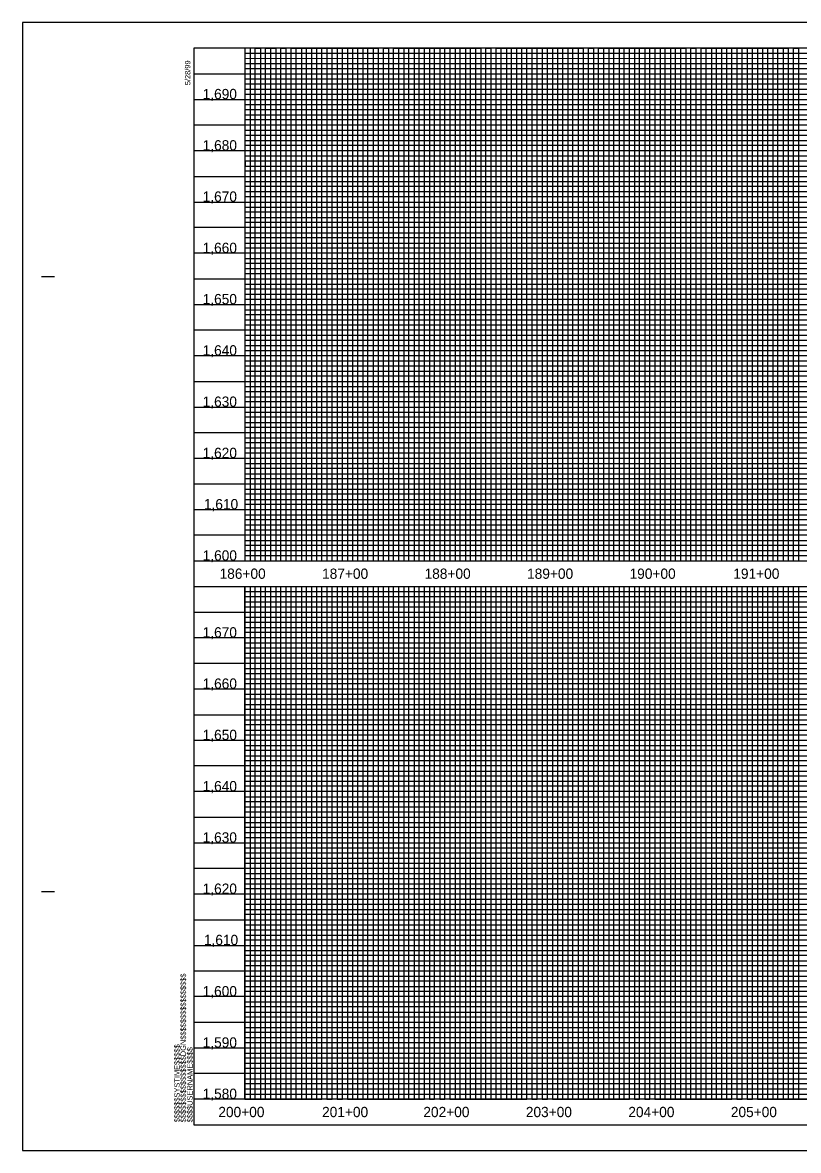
# Model space of a CAD drawing. Extents: x 505602 to 507286, y 483109 to 484209.
# Drawn here: x 505602 to 506359, y 483109 to 484209 of the extents above; entities that cross this region are included whole.
import ezdxf

# ---------------------------------------------------------------- set-up
doc = ezdxf.new("R2010")
doc.units = 0
for name, color, linetype in [('Exist Vertical Profile Vertical Axis Label', 7, 'Continuous'), ('Sheet Layout Profile Border Port 1', 7, 'Continuous'), ('Sheet Layout Profile Border Port 2', 7, 'Continuous'), ('Sheet Plot Border Outside CELL', 7, 'Continuous'), ('Sheet Profile CELL', 7, 'Continuous'), ('Sheet Profile Grid Major CELL', 7, 'Continuous'), ('Sheet Profile Grid Middle CELL', 7, 'Continuous'), ('Sheet Profile Grid Minor CELL', 7, 'Continuous')]:
    doc.layers.add(name, color=color, linetype=linetype)

msp = doc.modelspace()

# ---------------------------------------------------------------- linework, layer by layer
at = {"layer": 'Sheet Layout Profile Border Port 1'}
msp.add_lwpolyline([(505819.1, 484183.7), (505819.1, 483683.7), (507219.1, 483683.7), (507219.1, 484022.7), (507069, 484022.7), (507069, 484183.7)], close=True, dxfattribs=at)
at = {"layer": 'Sheet Layout Profile Border Port 2'}
msp.add_lwpolyline([(505819.1, 483658.7), (507219.1, 483658.7), (507219.1, 483158.7), (505819.1, 483158.7)], close=True, dxfattribs=at)
at = {"layer": 'Sheet Plot Border Outside CELL'}
msp.add_lwpolyline([(505602.1, 483108.7), (507286.1, 483108.7), (507286.1, 484208.7), (505602.1, 484208.7)], close=True, dxfattribs=at)
at = {"layer": 'Sheet Profile CELL'}
for p, q in [((505620.6, 483961.2), (505633.1, 483961.2)), ((505769.1, 483683.7), (507269.1, 483683.7)), ((505769.1, 483658.7), (507269.1, 483658.7)), ((505620.6, 483361.2), (505633.1, 483361.2)), ((507269.1, 483158.7), (505769.1, 483158.7)), ((505769.1, 483133.7), (507269.1, 483133.7)), ((505769.1, 483133.7), (505769.1, 483133.7)), ((505769.1, 483133.7), (505769.1, 483133.7)), ((505769.1, 483133.7), (505769.1, 483133.7)), ((505769.1, 483133.7), (505769.1, 483133.7)), ((505769.1, 483133.7), (505769.1, 483133.7)), ((505769.1, 483133.7), (505769.1, 483133.7)), ((505769.1, 483133.7), (505769.1, 483133.7))]:
    msp.add_line(p, q, dxfattribs=at)
msp.add_lwpolyline([(507269.1, 484183.7), (505769.1, 484183.7), (505769.1, 483133.7), (507269.1, 483133.7)], close=True, dxfattribs=at)
msp.add_lwpolyline([(505806.6, 483133.7), (505806.6, 483133.7)], dxfattribs=at)
at = {"layer": 'Sheet Profile Grid Major CELL'}
msp.add_line((506269.1, 483658.7), (506319.1, 483658.7), dxfattribs=at)
for points in [[(505819.1, 484183.7), (505819.1, 483683.7), (505869.1, 483683.7), (505869.1, 484183.7), (505919.1, 484183.7), (505919.1, 483683.7), (505969.1, 483683.7), (505969.1, 484183.7), (506019.1, 484183.7), (506019.1, 483683.7), (506069.1, 483683.7), (506069.1, 484183.7), (506119.1, 484183.7), (506119.1, 483683.7), (506169.1, 483683.7), (506169.1, 484183.7), (506219.1, 484183.7), (506219.1, 483683.7), (506269.1, 483683.7), (506269.1, 484183.7), (506319.1, 484183.7), (506319.1, 483683.7), (506369.1, 483683.7)], [(505769.1, 484133.7), (507069.1, 484133.7)], [(507069.1, 484083.7), (505769.1, 484083.7), (505769.1, 484033.7), (507069.1, 484033.7)], [(507269.1, 483983.7), (505769.1, 483983.7), (505769.1, 483933.7), (507269.1, 483933.7)], [(507269.1, 483883.7), (505769.1, 483883.7), (505769.1, 483833.7), (507269.1, 483833.7)], [(507269.1, 483783.7), (505769.1, 483783.7), (505769.1, 483783.7), (505769.1, 483733.7), (507269.1, 483733.7)], [(505819.1, 483658.7), (505819.1, 483158.7), (505869.1, 483158.7), (505869.1, 483658.7), (505919.1, 483658.7), (505919.1, 483158.7), (505969.1, 483158.7), (505969.1, 483658.7), (506019.1, 483658.7), (506019.1, 483158.7), (506069.1, 483158.7), (506069.1, 483658.7), (506119.1, 483658.7), (506119.1, 483158.7), (506169.1, 483158.7), (506169.1, 483658.7), (506219.1, 483658.7), (506219.1, 483158.7), (506269.1, 483158.7), (506269.1, 483658.7), (506319.1, 483658.7), (506319.1, 483158.7), (506369.1, 483158.7)], [(507269.1, 483608.7), (505769.1, 483608.7)], [(507269.1, 483558.7), (505769.1, 483558.7), (505769.1, 483508.7), (507269.1, 483508.7)], [(507269.1, 483458.7), (505769.1, 483458.7), (505769.1, 483408.7), (507269.1, 483408.7)], [(507269.1, 483358.7), (505769.1, 483358.7), (505769.1, 483308.7), (507269.1, 483308.7)], [(507269.1, 483258.7), (505769.1, 483258.7), (505769.1, 483258.7), (505769.1, 483208.7), (507269.1, 483208.7)], [(507269.1, 483158.7), (505769.1, 483158.7)]]:
    msp.add_lwpolyline(points, dxfattribs=at)
at = {"layer": 'Sheet Profile Grid Middle CELL'}
msp.add_line((505769.1, 484158.7), (507069, 484158.7), dxfattribs=at)
for points in [[(505844.1, 484183.7), (505844.1, 483683.7), (505894.1, 483683.7), (505894.1, 484183.7), (505944.1, 484183.7), (505944.1, 483683.7), (505994.1, 483683.7), (505994.1, 484183.7), (506044.1, 484183.7), (506044.1, 483683.7), (506094.1, 483683.7), (506094.1, 484183.7), (506144.1, 484183.7), (506144.1, 483683.7), (506194.1, 483683.7), (506194.1, 484183.7), (506244.1, 484183.7), (506244.1, 483683.7), (506294.1, 483683.7), (506294.1, 484183.7), (506344.1, 484183.7), (506344.1, 483683.7), (506394.1, 483683.7)], [(507069.1, 484108.7), (505769.1, 484108.7), (505769.1, 484058.7), (507069.1, 484058.7)], [(507269.1, 484008.7), (505769.1, 484008.7), (505769.1, 483958.7), (507094.1, 483958.7)], [(507269.1, 483908.7), (505769.1, 483908.7), (505769.1, 483858.7), (507269.1, 483858.7)], [(507269.1, 483808.7), (505769.1, 483808.7), (505769.1, 483758.7), (507269.1, 483758.7)], [(507269.1, 483708.7), (505769.1, 483708.7)], [(505794.1, 483658.7), (505844.1, 483658.7), (505844.1, 483158.7), (505894.1, 483158.7), (505894.1, 483658.7), (505944.1, 483658.7), (505944.1, 483158.7), (505994.1, 483158.7), (505994.1, 483658.7), (506044.1, 483658.7), (506044.1, 483158.7), (506094.1, 483158.7), (506094.1, 483658.7), (506144.1, 483658.7), (506144.1, 483158.7), (506194.1, 483158.7), (506194.1, 483658.7), (506244.1, 483658.7), (506244.1, 483158.7), (506294.1, 483158.7), (506294.1, 483658.7), (506344.1, 483658.7), (506344.1, 483158.7), (506394.1, 483158.7)], [(505769.1, 483633.7), (507269.1, 483633.7)], [(507269.1, 483583.7), (505769.1, 483583.7), (505769.1, 483533.7), (507269.1, 483533.7)], [(507269.1, 483483.7), (505769.1, 483483.7), (505769.1, 483433.7), (507269.1, 483433.7)], [(507269.1, 483383.7), (505769.1, 483383.7), (505769.1, 483333.7), (507269.1, 483333.7)], [(507269.1, 483283.7), (505769.1, 483283.7), (505769.1, 483233.7), (507269.1, 483233.7)], [(507269.1, 483183.7), (505769.1, 483183.7)]]:
    msp.add_lwpolyline(points, dxfattribs=at)
at = {"layer": 'Sheet Profile Grid Minor CELL'}
for p, q in [((505819.1, 484178.7), (507069.1, 484178.7)), ((505819.1, 484173.7), (505819.1, 484173.7)), ((507069.1, 484173.7), (505819.1, 484173.4)), ((505819.1, 484168.7), (507069.1, 484168.7)), ((507069, 484048.7), (505819.1, 484048.7)), ((507069.1, 484043.7), (505819.1, 484043.7)), ((507069.1, 484038.7), (505819.1, 484038.7)), ((505819.1, 484028.7), (507069.1, 484028.7)), ((507069.1, 484023.7), (505819.1, 484023.7)), ((505819.1, 484018.7), (507219.1, 484018.7)), ((507219.1, 483998.7), (505819.1, 483998.7)), ((505819.1, 483993.7), (507219.1, 483993.7)), ((507219.1, 483973.7), (505819.1, 483973.7)), ((505819.1, 483968.7), (507219.1, 483968.7)), ((507219.1, 483948.7), (505819.1, 483948.7)), ((505819.1, 483943.7), (507219.1, 483943.7)), ((507219.1, 483938.7), (505819.1, 483938.7)), ((505819.1, 483928.7), (507219.1, 483928.7)), ((507219.1, 483923.7), (505819.1, 483923.7)), ((505819.1, 483918.7), (507219.1, 483918.7)), ((507219.1, 483913.7), (505819.1, 483913.7)), ((505819.1, 483903.7), (507219.1, 483903.7)), ((507219.1, 483898.7), (505819.1, 483898.7)), ((505819.1, 483893.7), (507219.1, 483893.7)), ((507219.1, 483888.7), (505819.1, 483888.7)), ((505819.1, 483878.7), (507219.1, 483878.7)), ((507219.1, 483873.7), (505819.1, 483873.7)), ((505819.1, 483868.7), (507219.1, 483868.7)), ((507219.1, 483863.7), (505819.1, 483863.7)), ((505819.1, 483853.7), (507219.1, 483853.7)), ((507219.1, 483848.7), (505819.1, 483848.7)), ((505819.1, 483843.7), (507219.1, 483843.7)), ((507219.1, 483838.7), (505819.1, 483838.7)), ((505819.1, 483828.7), (507219.1, 483828.7)), ((507219.1, 483823.7), (505819.1, 483823.7)), ((505819.1, 483818.7), (507219.1, 483818.7)), ((507219.1, 483813.7), (505819.1, 483813.7)), ((505819.1, 483803.7), (507219.1, 483803.7)), ((507219.1, 483798.7), (505819.1, 483798.7)), ((507219.1, 483793.7), (505819.1, 483793.7)), ((507219.1, 483788.7), (505819.1, 483788.7)), ((505819.1, 483778.7), (507219.1, 483778.7)), ((507219.1, 483773.7), (505819.1, 483773.7)), ((505819.1, 483768.7), (507219.1, 483768.7)), ((507219.1, 483763.7), (505819.1, 483763.7)), ((505819.1, 483753.7), (507219.1, 483753.7)), ((507219.1, 483748.7), (505819.1, 483748.7)), ((505819.1, 483743.7), (507219.1, 483743.7)), ((507219.1, 483738.7), (505819.1, 483738.7)), ((505819.1, 483728.7), (507219.1, 483728.7)), ((507219.1, 483723.7), (505819.1, 483723.7)), ((505819.1, 483718.7), (507219.1, 483718.7)), ((507219.1, 483713.7), (505819.1, 483713.7)), ((505819.1, 483703.7), (507219.1, 483703.7)), ((507219.1, 483698.7), (505819.1, 483698.7)), ((505819.1, 483693.7), (507219.1, 483693.7)), ((505819.1, 483653.7), (507219.1, 483653.7)), ((507219.1, 483648.7), (505819.1, 483648.7)), ((505819.1, 483643.7), (507219.1, 483643.7)), ((507219.1, 483638.7), (505819.1, 483638.7)), ((505819.1, 483628.7), (507219.1, 483628.7)), ((507219.1, 483623.7), (505819.1, 483623.7)), ((505819.1, 483618.7), (507219.1, 483618.7)), ((507219.1, 483613.7), (505819.1, 483613.7)), ((505819.1, 483603.7), (507219.1, 483603.7)), ((507219.1, 483598.7), (505819.1, 483598.7)), ((505819.1, 483593.7), (507219.1, 483593.7)), ((507219.1, 483588.7), (505819.1, 483588.7)), ((505819.1, 483578.7), (507219.1, 483578.7)), ((507219.1, 483573.7), (505819.1, 483573.7)), ((505819.1, 483568.7), (507219.1, 483568.7)), ((507219.1, 483563.7), (505819.1, 483563.7)), ((505819.1, 483553.7), (507219.1, 483553.7)), ((507219.1, 483548.7), (505819.1, 483548.7)), ((505819.1, 483543.7), (507219.1, 483543.7)), ((507219.1, 483538.7), (505819.1, 483538.7)), ((505819.1, 483528.7), (507219.1, 483528.7)), ((507219.1, 483523.7), (505819.1, 483523.7)), ((505819.1, 483518.7), (507219.1, 483518.7)), ((507219.1, 483513.7), (505819.1, 483513.7)), ((505819.1, 483503.7), (507219.1, 483503.7)), ((507219.1, 483498.7), (505819.1, 483498.7)), ((505819.1, 483493.7), (507219.1, 483493.7)), ((507219.1, 483488.7), (505819.1, 483488.7)), ((505819.1, 483478.7), (507219.1, 483478.7)), ((507219.1, 483473.7), (505819.1, 483473.7)), ((505819.1, 483468.7), (507219.1, 483468.7)), ((507219.1, 483463.7), (505819.1, 483463.9)), ((505819.1, 483453.7), (507219.1, 483453.7)), ((507219.1, 483448.7), (505819.1, 483448.7)), ((505819.1, 483443.7), (507219.1, 483443.7)), ((507219.1, 483438.7), (505819.1, 483438.7)), ((505819.1, 483428.7), (507219.1, 483428.7)), ((507219.1, 483423.7), (505819.1, 483423.7)), ((505819.1, 483418.7), (507219.1, 483418.7)), ((507219.1, 483413.7), (505819.1, 483413.7)), ((505819.1, 483403.7), (507219.1, 483403.7)), ((507219.1, 483398.7), (505819.1, 483398.7)), ((505819.1, 483393.7), (507219.1, 483393.7)), ((507219.1, 483388.7), (505819.1, 483388.7)), ((505819.1, 483378.7), (507219.1, 483378.7)), ((507219.1, 483373.7), (505819.1, 483373.7)), ((505819.1, 483368.7), (507219.1, 483368.7)), ((507219.1, 483363.7), (505819.1, 483363.7)), ((505819.1, 483353.7), (507219.1, 483353.7)), ((507219.1, 483348.7), (505819.1, 483348.7)), ((505819.1, 483343.7), (507219.1, 483343.7)), ((507219.1, 483338.7), (505819.1, 483338.7)), ((505819.1, 483328.7), (507219.1, 483328.7)), ((507219.1, 483323.7), (505819.1, 483323.7)), ((505819.1, 483318.7), (507219.1, 483318.7)), ((507219.1, 483313.7), (505819.1, 483313.7)), ((505819.1, 483303.7), (507219.1, 483303.7)), ((507219.1, 483298.7), (505819.1, 483298.7)), ((505819.1, 483293.7), (507219.1, 483293.7)), ((507219.1, 483288.7), (505819.1, 483288.7)), ((505819.1, 483278.7), (507219.1, 483278.7)), ((507219.1, 483273.7), (505819.1, 483273.7)), ((505819.1, 483268.7), (507219.1, 483268.7)), ((507219.1, 483263.7), (505819.1, 483263.7)), ((505819.1, 483253.7), (507219.1, 483253.7)), ((507219.1, 483248.7), (505819.1, 483248.7)), ((505819.1, 483243.7), (507219.1, 483243.7)), ((507219.1, 483238.7), (505819.1, 483238.7)), ((505819.1, 483228.7), (507219.1, 483228.7)), ((507219.1, 483223.7), (505819.1, 483223.7)), ((505819.1, 483218.7), (507219.1, 483218.7)), ((507219.1, 483213.7), (505819.1, 483213.7)), ((505819.1, 483203.7), (507219.1, 483203.7)), ((507219.1, 483198.7), (505819.1, 483198.7)), ((505819.1, 483193.7), (507219.1, 483193.7)), ((507219.1, 483188.7), (505819.1, 483188.7)), ((505819.1, 483178.7), (507219.1, 483178.7)), ((507219.1, 483173.7), (505819.1, 483173.7)), ((505819.1, 483168.7), (507219.1, 483168.7)), ((505819.1, 483163.7), (507219.1, 483163.7))]:
    msp.add_line(p, q, dxfattribs=at)
for points in [[(505824.1, 484183.7), (505824.1, 483683.7), (505829.1, 483683.7), (505829.1, 484183.7), (505834.1, 484183.7), (505834.1, 483683.7), (505839.1, 483683.7), (505839.1, 484183.7), (505849.1, 484183.7), (505849.1, 483683.7), (505854.1, 483683.7), (505854.1, 484183.7), (505859.1, 484183.7), (505859.1, 483683.7), (505864.1, 483683.7), (505874.1, 483683.7), (505879.1, 483683.7), (505879.1, 484183.7), (505884.1, 484183.7), (505884.1, 483683.7), (505889.1, 483683.7), (505889.1, 484183.7), (505899.1, 484183.7), (505899.1, 483683.7), (505904.1, 483683.7), (505904.1, 484183.7), (505909.1, 484183.7), (505909.1, 483683.7), (505914.1, 483683.7), (505914.1, 484183.7), (505924.1, 484183.7), (505924.1, 483683.7), (505929.1, 483683.7), (505929.1, 484183.7), (505934.1, 484183.7), (505934.1, 483683.7), (505939.1, 483683.7), (505939.1, 484183.7), (505949.1, 484183.7), (505949.1, 483683.7), (505954.1, 483683.7), (505954.1, 484183.7), (505959.1, 484183.7), (505959.1, 483683.7), (505964.1, 483683.7), (505964.1, 484183.7), (505974.1, 484183.7), (505974.1, 483683.7), (505979.1, 483683.7), (505979.1, 484183.7), (505984.1, 484183.7), (505984.1, 483683.7), (505989.1, 483683.7), (505989.1, 484183.7), (505999.1, 484183.7), (505999.1, 483683.7), (506004.1, 483683.7), (506004.1, 484183.7), (506009.1, 484183.7), (506009.1, 483683.7), (506014.1, 483683.7), (506014.1, 484183.7), (506024.1, 484183.7), (506024.1, 483683.7), (506029.1, 483683.7), (506029.1, 484183.7), (506034.1, 484183.7), (506034.1, 483683.7)], [(505864.1, 483683.7), (505864.1, 484183.7), (505874.1, 484183.7), (505874.1, 483683.7)], [(506034.1, 483683.7), (506039.1, 483683.7), (506039.1, 484183.7), (506049.1, 484183.7), (506049.1, 483683.7), (506054.1, 483683.7), (506054.1, 484183.7), (506059.1, 484183.7), (506059.1, 483683.7), (506064.1, 483683.7), (506064.1, 484183.7), (506074.1, 484183.7), (506074.1, 483683.7), (506079.1, 483683.7), (506079.1, 484183.7), (506084.1, 484183.7), (506084.1, 483683.7), (506089.1, 483683.7), (506089.1, 484183.7), (506099.1, 484183.7), (506099.1, 483683.7), (506104.1, 483683.7), (506104.1, 484183.7), (506109.1, 484183.7), (506109.1, 483683.7), (506114.1, 483683.7), (506114.1, 484183.7), (506124.1, 484183.7), (506124.1, 483683.7), (506129.1, 483683.7), (506129.1, 484183.7), (506134.1, 484183.7), (506134.1, 483683.7), (506139.1, 483683.7), (506139.1, 484183.7), (506149.1, 484183.7), (506149.1, 483683.7), (506154.1, 483683.7), (506154.1, 484183.7), (506159.1, 484183.7), (506159.1, 483683.7), (506164.1, 483683.7), (506164.1, 484183.7), (506174.1, 484183.7), (506174.1, 483683.7), (506179.1, 483683.7), (506179.1, 484183.7), (506184.1, 484183.7), (506184.1, 483683.7), (506189.1, 483683.7), (506189.1, 484183.7), (506199.1, 484183.7), (506199.1, 483683.7), (506204.1, 483683.7), (506204.1, 484183.7), (506209.1, 484183.7), (506209.1, 483683.7), (506214.1, 483683.7), (506214.1, 484183.7), (506224.1, 484183.7), (506224.1, 483683.7), (506229.1, 483683.7), (506229.1, 484183.7), (506234.1, 484183.7), (506234.1, 483683.7), (506239.1, 483683.7), (506239.1, 484183.7), (506249.1, 484183.7), (506249.1, 483683.7), (506254.1, 483683.7), (506254.1, 484183.7), (506259.1, 484183.7), (506259.1, 483683.7), (506264.1, 483683.7), (506264.1, 484183.7), (506274.1, 484183.7), (506274.1, 483683.7), (506279.1, 483683.7), (506279.1, 484183.7), (506284.1, 484183.7), (506284.1, 483683.7), (506289.1, 483683.7), (506289.1, 484183.7), (506299.1, 484183.7), (506299.1, 483683.7), (506304.1, 483683.7), (506304.1, 484183.7), (506309.1, 484183.7), (506309.1, 483683.7), (506314.1, 483683.7), (506314.1, 484183.7), (506324.1, 484183.7), (506324.1, 483683.7), (506329.1, 483683.7), (506329.1, 484183.7), (506334.1, 484183.7), (506334.1, 483683.7), (506339.1, 483683.7), (506339.1, 484183.7), (506349.1, 484183.7)], [(506349.1, 484183.7), (506349.1, 483683.7), (506354.1, 483683.7), (506354.1, 484183.7), (506359.1, 484183.7), (506359.1, 483683.7), (506364.1, 483683.7)], [(507069.1, 484163.7), (505819.1, 484163.7), (505819.1, 484153.7), (507069.1, 484153.7)], [(507069, 484148.7), (505819.1, 484148.7), (505819.1, 484143.7), (507069.1, 484143.7)], [(507069.1, 484138.7), (505819.1, 484138.7), (505819.1, 484128.7), (507069.1, 484128.7)], [(507069.1, 484123.7), (505819.1, 484123.7), (505819.1, 484118.7), (507069.1, 484118.7)], [(507069.1, 484113.7), (505819.1, 484113.7), (505819.1, 484103.7), (507069.1, 484103.7)], [(507069.1, 484098.7), (505819.1, 484098.7), (505819.1, 484093.7), (507069.1, 484093.7)], [(507069.1, 484088.7), (505819.1, 484088.7), (505819.1, 484078.7), (507069.1, 484078.7)], [(507069.1, 484073.6), (505819.2, 484073.6), (505819.2, 484068.7), (507069.1, 484068.7)], [(507069.1, 484063.7), (505819.1, 484063.7), (505819.1, 484053.7), (507069.1, 484053.7)], [(507219.1, 484013.7), (505819.1, 484013.7), (505819.1, 484003.7), (507219.1, 484003.7)], [(507219.1, 483988.7), (505819.1, 483988.7), (505819.1, 483978.7), (507219.1, 483978.7)], [(507219.1, 483963.7), (505819.1, 483963.7), (505819.1, 483953.7), (507219.1, 483953.7)], [(507219.1, 483688.7), (505819.1, 483688.7)], [(505819.1, 483658.7), (505824.1, 483658.7), (505824.1, 483158.7), (505829.1, 483158.7), (505829.1, 483658.7), (505834.1, 483658.7), (505834.1, 483158.7), (505839.1, 483158.7), (505839.1, 483658.7), (505849.1, 483658.7), (505849.1, 483158.7), (505854.1, 483158.7), (505854.1, 483658.7), (505859.1, 483658.7), (505859.1, 483158.7), (505864.1, 483158.7), (505874.1, 483158.7), (505879.1, 483158.7), (505879.1, 483658.7), (505884.1, 483658.7), (505884.1, 483158.7), (505889.1, 483158.7), (505889.1, 483658.7), (505899.1, 483658.7), (505899.1, 483158.7), (505904.1, 483158.7), (505904.1, 483658.7), (505909.1, 483658.7), (505909.1, 483158.7), (505914.1, 483158.7), (505914.1, 483658.7), (505924.1, 483658.7), (505924.1, 483158.7), (505929.1, 483158.7), (505929.1, 483658.7), (505934.1, 483658.7), (505934.1, 483158.7), (505939.1, 483158.7), (505939.1, 483658.7), (505949.1, 483658.7), (505949.1, 483158.7), (505954.1, 483158.7), (505954.1, 483658.7), (505959.1, 483658.7), (505959.1, 483158.7), (505964.1, 483158.7), (505964.1, 483658.7), (505974.1, 483658.7), (505974.1, 483158.7), (505979.1, 483158.7), (505979.1, 483658.7), (505984.1, 483658.7), (505984.1, 483158.7), (505989.1, 483158.7), (505989.1, 483658.7), (505999.1, 483658.7), (505999.1, 483158.7), (506004.1, 483158.7), (506004.1, 483658.7), (506009.1, 483658.7), (506009.1, 483158.7), (506014.1, 483158.7), (506014.1, 483658.7), (506024.1, 483658.7), (506024.1, 483158.7), (506029.1, 483158.7), (506029.1, 483658.7), (506034.1, 483658.7), (506034.1, 483158.7)], [(505864.1, 483158.7), (505864.1, 483658.7), (505874.1, 483658.7), (505874.1, 483158.7)], [(506034.1, 483158.7), (506039.1, 483158.7), (506039.1, 483658.7), (506049.1, 483658.7), (506049.1, 483158.7), (506054.1, 483158.7), (506054.1, 483658.7), (506059.1, 483658.7), (506059.1, 483158.7), (506064.1, 483158.7), (506064.1, 483658.7), (506074.1, 483658.7), (506074.1, 483158.7), (506079.1, 483158.7), (506079.1, 483658.7), (506084.1, 483658.7), (506084.1, 483158.7), (506089.1, 483158.7), (506089.1, 483658.7), (506099.1, 483658.7), (506099.1, 483158.7), (506104.1, 483158.7), (506104.1, 483658.7), (506109.1, 483658.7), (506109.1, 483158.7), (506114.1, 483158.7), (506114.1, 483658.7), (506124.1, 483658.7), (506124.1, 483158.7), (506129.1, 483158.7), (506129.1, 483658.7), (506134.1, 483658.7), (506134.1, 483158.7), (506139.1, 483158.7), (506139.1, 483658.7), (506149.1, 483658.7), (506149.1, 483158.7), (506154.1, 483158.7), (506154.1, 483658.7), (506159.1, 483658.7), (506159.1, 483158.7), (506164.1, 483158.7), (506164.1, 483658.7), (506174.1, 483658.7), (506174.1, 483158.7), (506179.1, 483158.7), (506179.1, 483658.7), (506184.1, 483658.7), (506184.1, 483158.7), (506189.1, 483158.7), (506189.1, 483658.7), (506199.1, 483658.7), (506199.1, 483158.7), (506204.1, 483158.7), (506204.1, 483658.7), (506209.1, 483658.7), (506209.1, 483158.7), (506214.1, 483158.7), (506214.1, 483658.7), (506224.1, 483658.7), (506224.1, 483158.7), (506229.1, 483158.7), (506229.1, 483658.7), (506234.1, 483658.7), (506234.1, 483158.7), (506239.1, 483158.7), (506239.1, 483658.7), (506249.1, 483658.7), (506249.1, 483158.7), (506254.1, 483158.7), (506254.1, 483658.7), (506259.1, 483658.7), (506259.1, 483158.7), (506264.1, 483158.7), (506264.1, 483658.7), (506274.1, 483658.7), (506274.1, 483158.7), (506279.1, 483158.7), (506279.1, 483658.7), (506284.1, 483658.7), (506284.1, 483158.7), (506289.1, 483158.7), (506289.1, 483658.7), (506299.1, 483658.7), (506299.1, 483158.7), (506304.1, 483158.7), (506304.1, 483658.7), (506309.1, 483658.7), (506309.1, 483158.7), (506314.1, 483158.7), (506314.1, 483658.7), (506324.1, 483658.7), (506324.1, 483158.7), (506329.1, 483158.7), (506329.1, 483658.7), (506334.1, 483658.7), (506334.1, 483158.7), (506339.1, 483158.7), (506339.1, 483658.7), (506349.1, 483658.7)], [(506349.1, 483658.7), (506349.1, 483158.7), (506354.1, 483158.7), (506354.1, 483658.7), (506359.1, 483658.7), (506359.1, 483158.7), (506364.1, 483158.7)]]:
    msp.add_lwpolyline(points, dxfattribs=at)

# ---------------------------------------------------------------- texts
at = {"layer": 'Exist Vertical Profile Vertical Axis Label'}
for s, p in [('1,690', (505777.8, 484134)), ('1,680', (505777.8, 484084)), ('1,670', (505777.8, 484034)), ('1,660', (505777.8, 483984)), ('1,650', (505777.8, 483934)), ('1,640', (505777.8, 483884)), ('1,630', (505777.8, 483834)), ('1,620', (505777.8, 483784)), ('1,610', (505779, 483734)), ('1,600', (505777.8, 483684)), ('186+00', (505794.3, 483666.2)), ('187+00', (505894.3, 483666.2)), ('188+00', (505994.3, 483666.2)), ('189+00', (506094.3, 483666.2)), ('190+00', (506194.3, 483666.2)), ('191+00', (506295.5, 483666.2)), ('1,670', (505777.8, 483609)), ('1,660', (505777.8, 483559)), ('1,650', (505777.8, 483509)), ('1,640', (505777.8, 483459)), ('1,630', (505777.8, 483409)), ('1,620', (505777.8, 483359)), ('1,610', (505779, 483309)), ('1,600', (505777.8, 483259)), ('1,590', (505777.8, 483209)), ('1,580', (505777.8, 483159)), ('200+00', (505793.1, 483141.2)), ('201+00', (505894.3, 483141.2)), ('202+00', (505993.1, 483141.2)), ('203+00', (506093.1, 483141.2)), ('204+00', (506193.1, 483141.2)), ('205+00', (506293.1, 483141.2))]:
    msp.add_text(s, height=10, dxfattribs=at).set_placement(p)
at = {"layer": 'Sheet Profile CELL'}
for s, p in [('5/28/99', (505765.8, 484147.6)), ('$$$$$$$$$$$$$$$$DGN$$$$$$$$$$$$$$$$', (505761.4, 483136.1)), ('$$$$$$SYSTIME$$$$$', (505755.4, 483136.1)), ('$$$$USERNAME$$$$', (505768, 483136.1))]:
    msp.add_text(s, height=5.25, rotation=90, dxfattribs=at).set_placement(p)

doc.saveas('drawing.dxf')
